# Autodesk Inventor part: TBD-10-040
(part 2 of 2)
sketch "10-088"
  geometry: L1 (16.034, -12.25)-(25.632, -12.25) reference; L2 (25.632, -12.25)-(30.882, -7) reference; L3 (30.882, -7)-(37, -7) reference; L4 (37, -7)-(37, 7) reference; L5 (37, 7)-(30.882, 7) reference; L6 (30.882, 7)-(25.632, 12.25) reference; L7 (25.632, 12.25)-(16.034, 12.25) reference; L8 (16.034, 12.25)-(12.25, 16.034) reference; L9 (12.25, 16.034)-(12.25, 25.632) reference; L10 (12.25, 25.632)-(7, 30.882) reference; L11 (7, 30.882)-(7, 37) reference; L12 (7, 37)-(-7, 37) reference; L13 (-7, 37)-(-7, 30.882) reference; L14 (-7, 30.882)-(-12.25, 25.632) reference; L15 (-12.25, 25.632)-(-12.25, 16.034) reference; L16 (-12.25, 16.034)-(-16.034, 12.25) reference; L17 (-16.034, 12.25)-(-25.632, 12.25) reference; L18 (-25.632, 12.25)-(-30.882, 7) reference; L19 (-30.882, 7)-(-37, 7) reference; L20 (-37, 7)-(-37, -7) reference; L21 (-37, -7)-(-30.882, -7) reference; L22 (-30.882, -7)-(-25.632, -12.25) reference; L23 (-25.632, -12.25)-(-16.034, -12.25) reference; L24 (-16.034, -12.25)-(-12.25, -16.034) reference; L25 (-12.25, -16.034)-(-12.25, -25.632) reference; L26 (-12.25, -25.632)-(-7, -30.882) reference; L27 (-7, -30.882)-(-7, -37) reference; L28 (-7, -37)-(7, -37) reference; L29 (7, -37)-(7, -30.882) reference; L30 (7, -30.882)-(12.25, -25.632) reference; L31 (12.25, -25.632)-(12.25, -16.034) reference; L32 (12.25, -16.034)-(16.034, -12.25) reference; L33 (-13, -35.5)-(-16, -35.5) reference; L34 (-16, -35.5)-(-16, -40) reference; L35 (-16, -40)-(16, -40) reference; L36 (16, -40)-(16, -35.5) reference; L37 (16, -35.5)-(13, -35.5) reference; L38 (13, -35.5)-(13, -37) reference; L39 (13, -37)-(10, -37) reference; L40 (10, -37)-(10, -32.125) reference; L41 (10, -32.125)-(14.375, -27.75) reference; L42 (14.375, -27.75)-(20, -27.75) reference; L43 (20, -27.75)-(25.625, -27.75) reference; L44 (25.625, -27.75)-(30, -32.125) reference; L45 (30, -32.125)-(30, -37) reference; L46 (30, -37)-(27, -37) reference; L47 (27, -37)-(27, -35.5) reference; L48 (27, -35.5)-(24, -35.5) reference; L49 (24, -35.5)-(24, -40) reference; L50 (24, -40)-(37, -40) reference; L51 (37, -40)-(40, -37) reference; L52 (40, -37)-(40, -24) reference; L53 (40, -24)-(35.5, -24) reference; L54 (35.5, -24)-(35.5, -27) reference; L55 (35.5, -27)-(37, -27) reference; L56 (37, -27)-(37, -30) reference; L57 (37, -30)-(32.125, -30) reference; L58 (32.125, -30)-(27.75, -25.625) reference; L59 (27.75, -25.625)-(27.75, -20) reference; L60 (27.75, -20)-(27.75, -14.375) reference; L61 (27.75, -14.375)-(32.125, -10) reference; L62 (32.125, -10)-(37, -10) reference; L63 (37, -10)-(37, -13) reference; L64 (37, -13)-(35.5, -13) reference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; C1 r 3.4 at (-20, -20) reference; C2 r 3.4 at (-20, 20) reference; C3 r 3.4 at (20, -20) reference; C4 r 3.4 at (20, 20) reference; 1 further point
  constraints: 362 end point, 73 vertical, 72 horizontal, 4 centre point, 2 point on line, 227 other
extrude "Extrusion 10-088" sketch "10-088" stored distance "d93" = 10; taper "d94" = 0 deg
sketch "11-122"
  geometry: L1 (1.044, 56.086)-(-1.044, 56.086) reference; L2 (-1.044, 56.086)-(-12.75, 44.018) reference; L3 (-12.75, 44.018)-(-12.75, 36.998) reference; L4 (-12.75, 36.998)-(-1.044, 24.93) reference; L5 (-1.044, 24.93)-(1.044, 24.93) reference; L6 (1.044, 24.93)-(12.75, 36.998) reference; L7 (12.75, 36.998)-(12.75, 44.018) reference; L8 (12.75, 44.018)-(1.044, 56.086) reference; L9 (12.25, -44.889)-(12.25, -36.034) reference; L10 (12.25, -36.034)-(16.034, -32.25) reference; L11 (16.034, -32.25)-(24.889, -32.25) reference; L12 (24.889, -32.25)-(33, -23.888) reference; L13 (33, -23.888)-(33, -16.112) reference; L14 (33, -16.112)-(24.889, -7.75) reference; L15 (24.889, -7.75)-(16.034, -7.75) reference; L16 (16.034, -7.75)-(12.25, -3.966) reference; L17 (12.25, -3.966)-(12.25, 4.75) reference; L18 (12.25, 4.75)-(1.077, 15.588) reference; L19 (1.077, 15.588)-(-1.077, 15.588) reference; L20 (-1.077, 15.588)-(-12.25, 4.75) reference; L21 (-12.25, 4.75)-(-12.25, -3.966) reference; L22 (-12.25, -3.966)-(-16.034, -7.75) reference; L23 (-16.034, -7.75)-(-24.889, -7.75) reference; L24 (-24.889, -7.75)-(-33, -16.112) reference; L25 (-33, -16.112)-(-33, -23.888) reference; L26 (-33, -23.888)-(-24.889, -32.25) reference; L27 (-24.889, -32.25)-(-16.034, -32.25) reference; L28 (-16.034, -32.25)-(-12.25, -36.034) reference; L29 (-12.25, -36.034)-(-12.25, -44.889) reference; L30 (-12.25, -44.889)-(-3.888, -53) reference; L31 (-3.888, -53)-(3.888, -53) reference; L32 (3.888, -53)-(12.25, -44.889) reference; L33 (36.086, 18.956)-(36.086, 21.044) reference; L34 (36.086, 21.044)-(24.018, 32.75) reference; L35 (24.018, 32.75)-(16.998, 32.75) reference; L36 (16.998, 32.75)-(4.93, 21.044) reference; L37 (4.93, 21.044)-(4.93, 18.956) reference; L38 (4.93, 18.956)-(16.998, 7.25) reference; L39 (16.998, 7.25)-(24.018, 7.25) reference; L40 (24.018, 7.25)-(36.086, 18.956) reference; L41 (27.75, -3.374)-(27.75, 3.374) reference; L42 (27.75, 3.374)-(34.177, 10) reference; L43 (34.177, 10)-(35.5, 10) reference; L44 (35.5, 10)-(35.5, 4) reference; L45 (35.5, 4)-(40, 4) reference; L46 (40, 4)-(40, 36) reference; L47 (40, 36)-(35.5, 36) reference; L48 (35.5, 36)-(35.5, 30) reference; L49 (35.5, 30)-(34.177, 30) reference; L50 (34.177, 30)-(27.75, 36.626) reference; L51 (27.75, 36.626)-(27.75, 43.374) reference; L52 (27.75, 43.374)-(34.177, 50) reference; L53 (34.177, 50)-(35.5, 50) reference; L54 (35.5, 50)-(35.5, 44) reference; L55 (35.5, 44)-(40, 44) reference; L56 (40, 44)-(40, 57) reference; L57 (40, 57)-(37, 60) reference; L58 (37, 60)-(24, 60) reference; L59 (24, 60)-(24, 55.5) reference; L60 (24, 55.5)-(30, 55.5) reference; L61 (30, 55.5)-(30, 54.177) reference; L62 (30, 54.177)-(23.374, 47.75) reference; L63 (23.374, 47.75)-(16.626, 47.75) reference; L64 (16.626, 47.75)-(10, 54.177) reference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; C1 r 3.4 at (-20, -40) reference; C2 r 3.4 at (-20, 0) reference; C3 r 3.4 at (-20, 40) reference; C4 r 3.4 at (20, -40) reference; C5 r 3.4 at (20, 0) reference; C6 r 3.4 at (20, 40) reference; 1 further point
  constraints: 312 end point, 54 horizontal, 54 vertical, 6 centre point, 217 other
extrude "Extrusion 11-122" sketch "11-122" stored distance "d95" = 10; taper "d96" = 0 deg
sketch "10-122"
  geometry: L1 (38.22, 56.263)-(38.22, 51.78) reference; L2 (36.263, 58.22)-(38.22, 56.263) reference; L3 (31.78, 58.22)-(36.263, 58.22) reference; L4 (31.78, 51.78)-(31.78, 58.22) reference; L5 (38.22, 51.78)-(31.78, 51.78) reference; L6 (-38.22, -56.263)-(-38.22, -51.78) reference; L7 (-36.263, -58.22)-(-38.22, -56.263) reference; L8 (-31.78, -58.22)-(-36.263, -58.22) reference; L9 (-31.78, -51.78)-(-31.78, -58.22) reference; L10 (-38.22, -51.78)-(-31.78, -51.78) reference; L11 (-31.78, 58.22)-(-31.78, 51.78) reference; L12 (-36.263, 58.22)-(-31.78, 58.22) reference; L13 (-38.22, 56.263)-(-36.263, 58.22) reference; L14 (-38.22, 51.78)-(-38.22, 56.263) reference; L15 (-31.78, 51.78)-(-38.22, 51.78) reference; L16 (31.78, -58.22)-(31.78, -51.78) reference; L17 (36.263, -58.22)-(31.78, -58.22) reference; L18 (38.22, -56.263)-(36.263, -58.22) reference; L19 (38.22, -51.78)-(38.22, -56.263) reference; L20 (31.78, -51.78)-(38.22, -51.78) reference; L21 (1.882, 24)-(-1.882, 24) reference; L22 (12.25, 34.368)-(1.882, 24) reference; L23 (12.25, 45.632)-(12.25, 34.368) reference; L24 (7, 50.882)-(12.25, 45.632) reference; L25 (7, 57)-(7, 50.882) reference; L26 (-7, 57)-(7, 57) reference; L27 (-7, 50.882)-(-7, 57) reference; L28 (-12.25, 45.632)-(-7, 50.882) reference; L29 (-12.25, 34.368)-(-12.25, 45.632) reference; L30 (-1.882, 24)-(-12.25, 34.368) reference; L31 (-4, 21.882)-(-4, 18.118) reference; L32 (-14.368, 32.25)-(-4, 21.882) reference; L33 (-25.632, 32.25)-(-14.368, 32.25) reference; L34 (-30.882, 27)-(-25.632, 32.25) reference; L35 (-37, 27)-(-30.882, 27) reference; L36 (-37, 13)-(-37, 27) reference; L37 (-30.882, 13)-(-37, 13) reference; L38 (-25.632, 7.75)-(-30.882, 13) reference; L39 (-14.368, 7.75)-(-25.632, 7.75) reference; L40 (-4, 18.118)-(-14.368, 7.75) reference; L41 (25.632, 7.75)-(14.368, 7.75) reference; L42 (30.882, 13)-(25.632, 7.75) reference; L43 (37, 13)-(30.882, 13) reference; L44 (37, 27)-(37, 13) reference; L45 (30.882, 27)-(37, 27) reference; L46 (25.632, 32.25)-(30.882, 27) reference; L47 (14.368, 32.25)-(25.632, 32.25) reference; L48 (4, 21.882)-(14.368, 32.25) reference; L49 (4, 18.118)-(4, 21.882) reference; L50 (14.368, 7.75)-(4, 18.118) reference; L51 (-16.034, -7.75)-(-12.25, -3.966) reference; L52 (-25.632, -7.75)-(-16.034, -7.75) reference; L53 (-30.882, -13)-(-25.632, -7.75) reference; L54 (-37, -13)-(-30.882, -13) reference; L55 (-37, -27)-(-37, -13) reference; L56 (-30.882, -27)-(-37, -27) reference; L57 (-25.632, -32.25)-(-30.882, -27) reference; L58 (-16.034, -32.25)-(-25.632, -32.25) reference; L59 (-12.25, -36.034)-(-16.034, -32.25) reference; L60 (-12.25, -45.632)-(-12.25, -36.034) reference; L61 (-7, -50.882)-(-12.25, -45.632) reference; L62 (-7, -57)-(-7, -50.882) reference; L63 (7, -57)-(-7, -57) reference; L64 (7, -50.882)-(7, -57) reference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; C1 r 3.4 at (-20, 40) reference; C2 r 3.4 at (-20, 0) reference; C3 r 3.4 at (-20, -40) reference; C4 r 3.4 at (20, 40) reference; C5 r 3.4 at (20, 0) reference; C6 r 3.4 at (20, -40) reference; 1 further point
  constraints: 456 end point, 90 horizontal, 86 vertical, 6 centre point, 293 other
extrude "Extrusion 10-122" sketch "10-122" stored distance "d101" = 10; taper "d102" = 0 deg
sketch "11-160"
  geometry: L1 (-3.888, -73)-(-12.25, -64.889) reference; L2 (-12.25, -64.889)-(-12.25, -56.034) reference; L3 (-12.25, -56.034)-(-16.034, -52.25) reference; L4 (-16.034, -52.25)-(-24.889, -52.25) reference; L5 (-24.889, -52.25)-(-33, -43.888) reference; L6 (-33, -43.888)-(-33, -36.112) reference; L7 (-33, -36.112)-(-24.889, -27.75) reference; L8 (-24.889, -27.75)-(-16.034, -27.75) reference; L9 (-16.034, -27.75)-(-12.25, -23.966) reference; L10 (-12.25, -23.966)-(-12.25, -15.111) reference; L11 (-12.25, -15.111)-(-3.888, -7) reference; L12 (-3.888, -7)-(3.888, -7) reference; L13 (3.888, -7)-(12.25, -15.111) reference; L14 (12.25, -15.111)-(12.25, -23.966) reference; L15 (12.25, -23.966)-(16.034, -27.75) reference; L16 (16.034, -27.75)-(24.889, -27.75) reference; L17 (24.889, -27.75)-(33, -36.112) reference; L18 (33, -36.112)-(33, -43.888) reference; L19 (33, -43.888)-(24.889, -52.25) reference; L20 (24.889, -52.25)-(16.034, -52.25) reference; L21 (16.034, -52.25)-(12.25, -56.034) reference; L22 (12.25, -56.034)-(12.25, -64.889) reference; L23 (12.25, -64.889)-(3.888, -73) reference; L24 (3.888, -73)-(-3.888, -73) reference; L25 (-35.5, -10)-(-34.177, -10) reference; L26 (-34.177, -10)-(-27.75, -16.626) reference; L27 (-27.75, -16.626)-(-27.75, -23.374) reference; L28 (-27.75, -23.374)-(-34.177, -30) reference; L29 (-34.177, -30)-(-35.5, -30) reference; L30 (-35.5, -30)-(-35.5, -24) reference; L31 (-35.5, -24)-(-40, -24) reference; L32 (-40, -24)-(-40, -56) reference; L33 (-40, -56)-(-35.5, -56) reference; L34 (-35.5, -56)-(-35.5, -50) reference; L35 (-35.5, -50)-(-34.177, -50) reference; L36 (-34.177, -50)-(-27.75, -56.626) reference; L37 (-27.75, -56.626)-(-27.75, -63.374) reference; L38 (-27.75, -63.374)-(-34.177, -70) reference; L39 (-34.177, -70)-(-35.5, -70) reference; L40 (-35.5, -70)-(-35.5, -64) reference; L41 (-35.5, -64)-(-40, -64) reference; L42 (-40, -64)-(-40, -77) reference; L43 (-40, -77)-(-37, -80) reference; L44 (-37, -80)-(-24, -80) reference; L45 (-24, -80)-(-24, -75.5) reference; L46 (-24, -75.5)-(-30, -75.5) reference; L47 (-30, -75.5)-(-30, -74.177) reference; L48 (-30, -74.177)-(-23.374, -67.75) reference; L49 (-23.374, -67.75)-(-16.626, -67.75) reference; L50 (-16.626, -67.75)-(-10, -74.177) reference; L51 (-10, -74.177)-(-10, -75.5) reference; L52 (-10, -75.5)-(-16, -75.5) reference; L53 (-16, -75.5)-(-16, -80) reference; L54 (-16, -80)-(16, -80) reference; L55 (16, -80)-(16, -75.5) reference; L56 (16, -75.5)-(10, -75.5) reference; L57 (10, -75.5)-(10, -74.177) reference; L58 (10, -74.177)-(16.626, -67.75) reference; L59 (16.626, -67.75)-(23.374, -67.75) reference; L60 (23.374, -67.75)-(30, -74.177) reference; L61 (30, -74.177)-(30, -75.5) reference; L62 (30, -75.5)-(24, -75.5) reference; L63 (24, -75.5)-(24, -80) reference; L64 (24, -80)-(37, -80) reference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; C1 r 3.4 at (-20, -60) reference; C2 r 3.4 at (-20, -20) reference; C3 r 3.4 at (-20, 20) reference; C4 r 3.4 at (-20, 60) reference; C5 r 3.4 at (20, -60) reference; C6 r 3.4 at (20, -20) reference; C7 r 3.4 at (20, 20) reference; C8 r 3.4 at (20, 60) reference; 1 further point
  constraints: 384 end point, 66 horizontal, 66 vertical, 8 centre point, 269 other
extrude "Extrusion 11-160" sketch "11-160" stored distance "d97" = 10; taper "d98" = 0 deg
sketch "10-160"
  geometry: L1 (4.246, -2.121)-(14.375, -12.25) reference; L2 (14.375, -12.25)-(25.632, -12.25) reference; L3 (25.632, -12.25)-(30.882, -7) reference; L4 (30.882, -7)-(37, -7) reference; L5 (37, -7)-(37, 7) reference; L6 (37, 7)-(30.882, 7) reference; L7 (30.882, 7)-(25.632, 12.25) reference; L8 (25.632, 12.25)-(14.375, 12.25) reference; L9 (14.375, 12.25)-(4.246, 2.121) reference; L10 (4.246, 2.121)-(4.246, -2.121) reference; L11 (-4.246, -2.121)-(-14.375, -12.25) reference; L12 (-14.375, -12.25)-(-25.632, -12.25) reference; L13 (-25.632, -12.25)-(-30.882, -7) reference; L14 (-30.882, -7)-(-37, -7) reference; L15 (-37, -7)-(-37, 7) reference; L16 (-37, 7)-(-30.882, 7) reference; L17 (-30.882, 7)-(-25.632, 12.25) reference; L18 (-25.632, 12.25)-(-14.375, 12.25) reference; L19 (-14.375, 12.25)-(-4.246, 2.121) reference; L20 (-4.246, 2.121)-(-4.246, -2.121) reference; L21 (35.5, -16)-(40, -16) reference; L22 (40, -16)-(40, 16) reference; L23 (40, 16)-(35.5, 16) reference; L24 (35.5, 16)-(35.5, 13) reference; L25 (35.5, 13)-(37, 13) reference; L26 (37, 13)-(37, 10) reference; L27 (37, 10)-(32.125, 10) reference; L28 (32.125, 10)-(27.75, 14.375) reference; L29 (27.75, 14.375)-(27.75, 20) reference; L30 (27.75, 20)-(27.75, 25.625) reference; L31 (27.75, 25.625)-(32.125, 30) reference; L32 (32.125, 30)-(37, 30) reference; L33 (37, 30)-(37, 27) reference; L34 (37, 27)-(35.5, 27) reference; L35 (35.5, 27)-(35.5, 24) reference; L36 (35.5, 24)-(40, 24) reference; L37 (40, 24)-(40, 56) reference; L38 (40, 56)-(35.5, 56) reference; L39 (35.5, 56)-(35.5, 53) reference; L40 (35.5, 53)-(37, 53) reference; L41 (37, 53)-(37, 50) reference; L42 (37, 50)-(32.125, 50) reference; L43 (32.125, 50)-(27.75, 54.375) reference; L44 (27.75, 54.375)-(27.75, 60) reference; L45 (27.75, 60)-(27.75, 65.625) reference; L46 (27.75, 65.625)-(32.125, 70) reference; L47 (32.125, 70)-(37, 70) reference; L48 (37, 70)-(37, 67) reference; L49 (37, 67)-(35.5, 67) reference; L50 (35.5, 67)-(35.5, 64) reference; L51 (35.5, 64)-(40, 64) reference; L52 (40, 64)-(40, 77) reference; L53 (40, 77)-(37, 80) reference; L54 (37, 80)-(24, 80) reference; L55 (24, 80)-(24, 75.5) reference; L56 (24, 75.5)-(27, 75.5) reference; L57 (27, 75.5)-(27, 77) reference; L58 (27, 77)-(30, 77) reference; L59 (30, 77)-(30, 72.125) reference; L60 (30, 72.125)-(25.625, 67.75) reference; L61 (25.625, 67.75)-(20, 67.75) reference; L62 (20, 67.75)-(14.375, 67.75) reference; L63 (14.375, 67.75)-(10, 72.125) reference; L64 (10, 72.125)-(10, 77) reference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; C1 r 3.4 at (20, -60) reference; C2 r 3.4 at (20, -20) reference; C3 r 3.4 at (-20, -60) reference; C4 r 3.4 at (-20, -20) reference; C5 r 3.4 at (20, 20) reference; C6 r 3.4 at (20, 60) reference; C7 r 3.4 at (-20, 20) reference; C8 r 3.4 at (-20, 60) reference; 1 further point
  constraints: 580 end point, 116 horizontal, 110 vertical, 8 centre point, 4 point on line, 373 other
extrude "Extrusion 10-160" sketch "10-160" stored distance "d99" = 10; taper "d100" = 0 deg
body "Solid1"
workplane "Work Plane3"
workplane "Work Plane4"
other parameters: "d60" = 38
